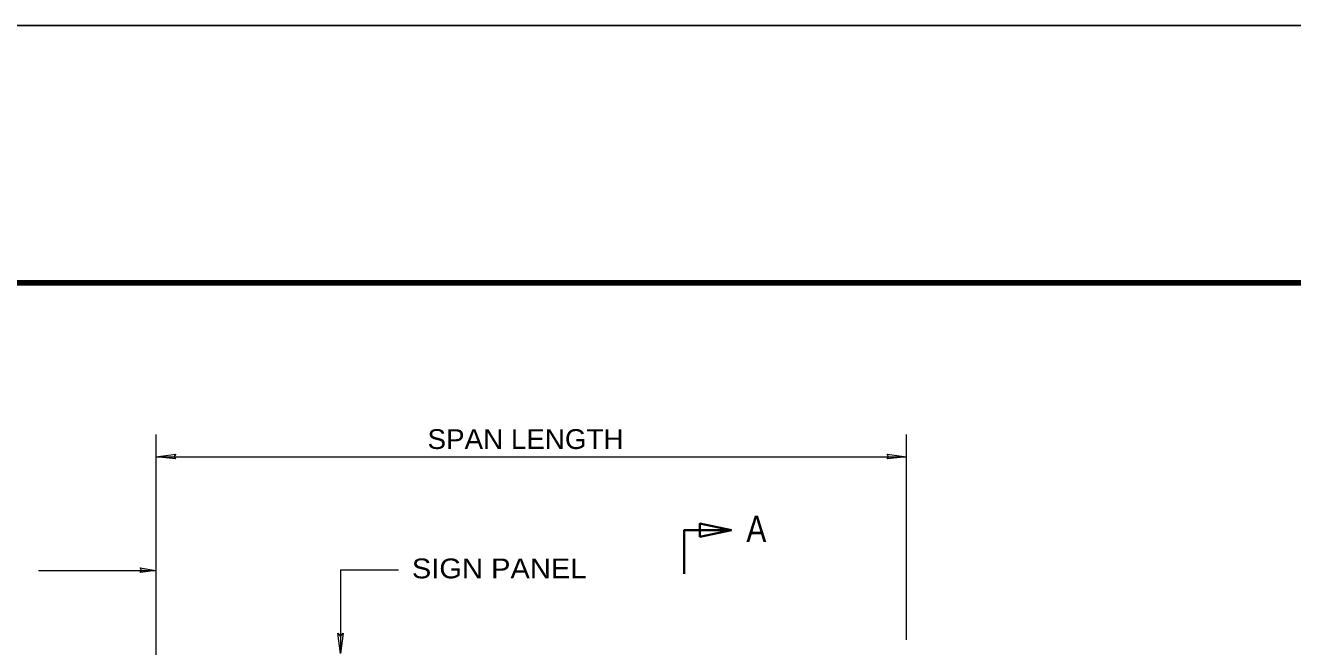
# Model space of a CAD drawing. Extents: x 312601.858 to 312602.699, y 144420.109 to 144420.704.
# Drawn here: x 312601.9635 to 312602.1557, y 144420.6093 to 144420.7035 of the extents above; entities that cross this region are included whole.
import ezdxf
from ezdxf.enums import TextEntityAlignment as Align

# ---------------------------------------------------------------- set-up
doc = ezdxf.new("R2010")
doc.units = 0
doc.header["$LTSCALE"] = 0.0012
for name, color, linetype, lineweight in [('1', 7, 'Continuous', 25), ('2', 7, 'Continuous', 25), ('39', 7, 'Continuous', 13)]:
    doc.layers.add(name, color=color, linetype=linetype, lineweight=lineweight)

msp = doc.modelspace()

# ---------------------------------------------------------------- hatches: boundary and pattern name
at = {"layer": '39'}
msp.add_hatch(color=256, dxfattribs=at).paths.add_polyline_path([(312601.9811, 144420.6209), (312601.9809, 144420.6213), (312601.9833, 144420.6209), (312601.9809, 144420.6206)])

# ---------------------------------------------------------------- linework, layer by layer
at = {"layer": '1', "lineweight": 13}
for p, q in [((312601.9833, 144420.6415), (312601.9833, 144420.6018)), ((312601.9833, 144420.6381), (312602.0971, 144420.6381)), ((312602.0113, 144420.621), (312602.0113, 144420.6083)), ((312602.0113, 144420.621), (312602.0201, 144420.621))]:
    msp.add_line(p, q, dxfattribs=at)
for points in [[(312601.9863, 144420.6378), (312601.9833, 144420.6381), (312601.9863, 144420.6385), (312601.986, 144420.6381)], [(312602.0942, 144420.6385), (312602.0971, 144420.6381), (312602.0942, 144420.6378), (312602.0944, 144420.6381)], [(312602.0117, 144420.6114), (312602.0113, 144420.6083), (312602.0109, 144420.6114), (312602.0113, 144420.6109)]]:
    msp.add_lwpolyline(points, close=True, dxfattribs=at)
at = {"layer": '2', "lineweight": 13}
for p, q in [((312602.0971, 144420.6104), (312602.0971, 144420.6415)), ((312601.9655, 144420.6209), (312601.9833, 144420.6209))]:
    msp.add_line(p, q, dxfattribs=at)
at = {"layer": '39', "lineweight": 25}
msp.add_line((312601.8578, 144420.7035), (312602.6988, 144420.7035), dxfattribs=at)
at = {"layer": '39', "lineweight": 158}
msp.add_line((312601.9088, 144420.6645), (312602.6838, 144420.6645), dxfattribs=at)
at = {"layer": '39', "lineweight": 35}
msp.add_lwpolyline([(312602.0704, 144420.627), (312602.0634, 144420.627), (312602.0634, 144420.6204)], dxfattribs=at)
msp.add_lwpolyline([(312602.0706, 144420.627), (312602.0658, 144420.628), (312602.0658, 144420.626)], close=True, dxfattribs=at)
at = {"layer": '39'}
for points in [[(312602.0658, 144420.626), (312602.0706, 144420.627), (312602.0658, 144420.628)], [(312601.9811, 144420.6209), (312601.9809, 144420.6213), (312601.9833, 144420.6209), (312601.9809, 144420.6206)]]:
    msp.add_lwpolyline(points, close=True, dxfattribs=at)

# ---------------------------------------------------------------- texts
at = {"layer": '1'}
for s, height, width, p in [('SPAN LENGTH', 0.003, 1.05, (312602.03935, 144420.6393)), ('A', 0.004, 0.85, (312602.07435, 144420.6252)), ('SIGN PANEL', 0.003, 1.1, (312602.03535, 144420.6197))]:
    msp.add_text(s, height=height, dxfattribs=dict(at, width=width)).set_placement(p, align=Align.CENTER)

doc.saveas('drawing.dxf')
